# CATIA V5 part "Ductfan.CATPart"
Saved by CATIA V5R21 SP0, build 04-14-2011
Part number: Ductfan
Bounding box of the stored display mesh (mm): x -484.456 to 434.709, y -40 to 160, z -434.709 to 434.709
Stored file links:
  C:\Users\andre\OneDrive\Documentos\UNB-FGA\3_Semestre\Sistemas Aeroespaciais\Ductfan.CATPart
  C:\Users\andre\AppData\Local\Temp\Rar$DIa18808.12376\NACA 2412 3D Aerofoil.CATPart
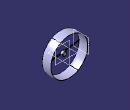
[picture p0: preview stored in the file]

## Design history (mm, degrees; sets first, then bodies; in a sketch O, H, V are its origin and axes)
Body1 (main body)
  Sketch1 on yz-plane, origin (0, 0, 0), H (0, 1, 0), V (0, 0, 1)
    point P1 (-40, -426.309)
    point P2 (160, -426.309)
    unspec C1
    unspec C2
    axis line L1 (0, -34.7251) -> (0, -104.5277)
    distance P1 P2 = 200
    distance C1 C2 = 23.9924
    distance P1 L1 = 40
    distance C1 H = 410.464
    vertical: L1 V
    coincidence: L1 V
  Shaft1: profile Sketch1, axis Sketch1.H, angle 360
  Sketch2 on zx-plane, origin (0, 0, 0), H (-1, 0, 0), V (0, 0, 1)
    circle A1 centre (0, 0) radius 50
    radius A1 = 50
  Pad1: profile Sketch2, direction (0, 1, 0), length 60
  Fillet1: radius 10, on edge [face of Pad1 from Sketch2.A1 | end face of Pad1]
  Sketch3 on start face of Pad1, origin (0, 0, 0), H (1, 0, 0), V (0, 0, 1)
    circle A1 centre (0, 0) radius 11.5
    point P1 (11.5, 0)
    radius A1 = 11.5
    coincidence: A1 P1, P1 H
  Pocket1: profile Sketch3, direction (0, 1, 0), length 10
  Sketch4 on start face of Pad1, origin (0, 0, 0), H (1, 0, 0), V (0, 0, 1)
    ellipse A1 centre (0, 0) semi-axes 406.4, 10 rotation 172.047
    "Radius" A1 = 406.4
    distance A1 O = 10
  Pad2: profile Sketch4, direction (0, -1, 0), length 10
  Plane1: type Offset, RefPlane yz-plane, Offset 434.456, reversed
  Sketch5 on Plane1, origin (-434.456, 0, 0), H (0, 1, 0), V (0, 0, 1)
    point P1 (-40, -2.4533)
    point P2 (160, -2.4533)
    unspec C1
    unspec C2
    circle A1 centre (0, 0) radius 5
    point P3 (0, 0)
    circle A2 centre (60.03, -0.0038) radius 5
    point P4 (60.03, -0.0038)
    distance P1 P2 = 200
    distance P1 V = 40
    radius A1 = 5
    distance C1 C2 = 23.9924
    distance P3 C1 = 11.996
    distance P3 P1 = 40.0752
    radius A2 = 5
    distance P4 P2 = 100
    distance P4 C1 = 11.996
    distance P3 H = 0
    coincidence: P3 V
  Pad3: profile Sketch5, direction (-1, 0, 0), length 50
  Fillet2: radius 1, on edge [face of Pad2 from Sketch4.A1 | end face of Pad2]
